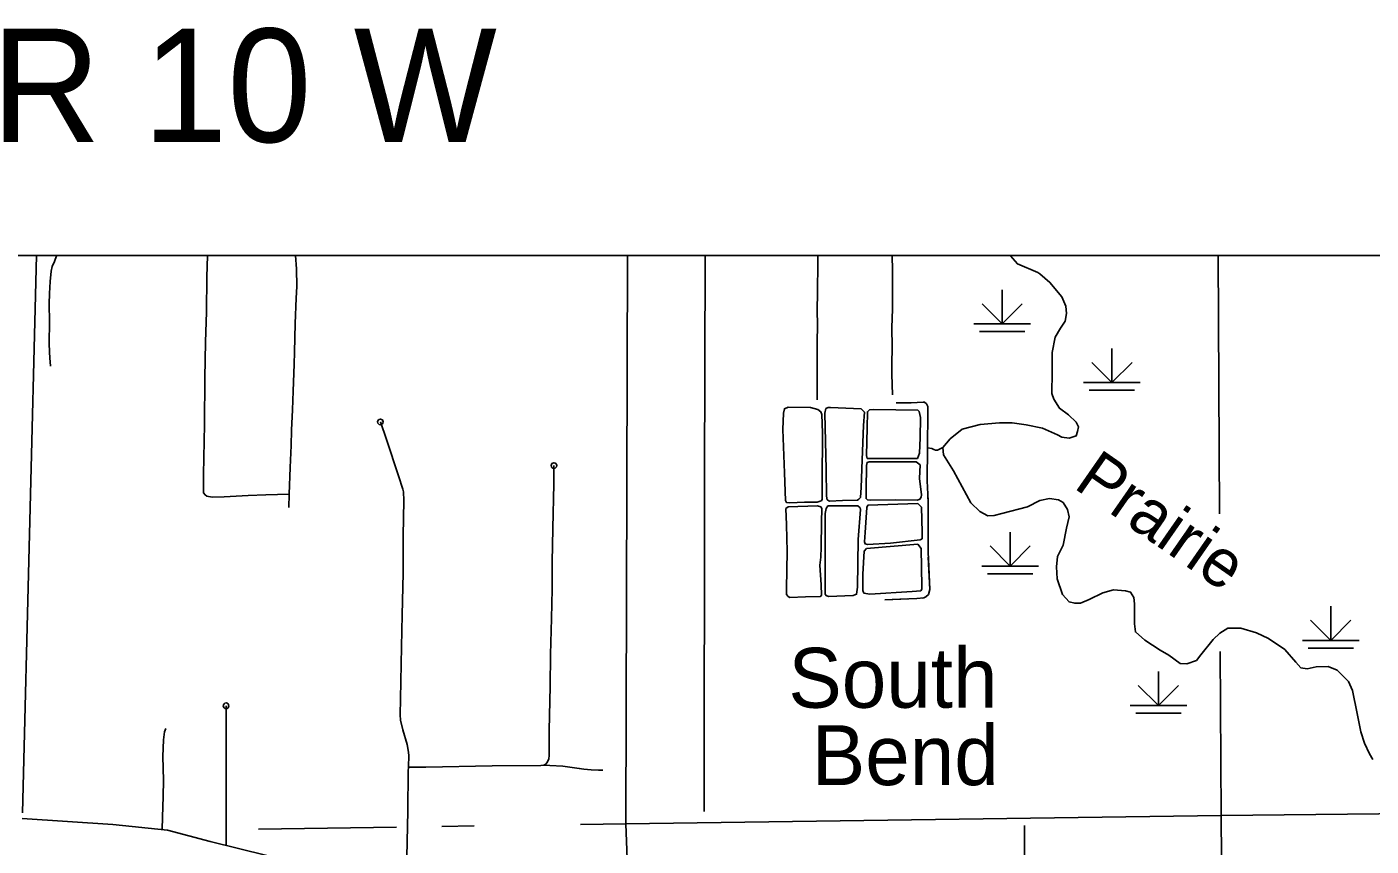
# Model space of a CAD drawing. Extents: x 1127717 to 1741049, y 2026793 to 2244711.
# Drawn here: x 1289221 to 1301075, y 2106736 to 2113957 of the extents above; entities that cross this region are included whole.
import ezdxf

# ---------------------------------------------------------------- set-up
doc = ezdxf.new("R2010")
doc.units = 0
for name, color, linetype in [('1', 7, 'Continuous'), ('10', 7, 'Continuous'), ('2', 7, 'Continuous'), ('24', 7, 'Continuous'), ('31', 7, 'Continuous'), ('32', 7, 'Continuous'), ('35', 7, 'Continuous'), ('43', 7, 'Continuous'), ('44', 7, 'Continuous'), ('5', 7, 'Continuous'), ('R_Draft', 7, 'Continuous')]:
    doc.layers.add(name, color=color, linetype=linetype)

msp = doc.modelspace()

# ---------------------------------------------------------------- linework, layer by layer
at = {"layer": '1'}
msp.add_lwpolyline([(1349634, 2111942), (1278363, 2111942), (1278363, 2066677), (1349634, 2066677)], close=True, dxfattribs=at)
at = {"layer": '10'}
msp.add_lwpolyline([(1289179, 2106981), (1289979, 2106928), (1290461, 2106877), (1290836, 2106777), (1291337, 2106654)], dxfattribs=at)
at = {"layer": '2'}
msp.add_lwpolyline([(1289181, 2107030), (1289306, 2111942)], dxfattribs=at)
at = {"layer": '31'}
for points in [[(1289483, 2111942), (1289482, 2111938), (1289464, 2111889), (1289443, 2111844), (1289435, 2111803), (1289427, 2111713), (1289421, 2111608), (1289417, 2111517), (1289419, 2111357), (1289417, 2111169), (1289419, 2111091), (1289423, 2111041), (1289429, 2110967)], [(1290813, 2111942), (1290809, 2111750), (1290805, 2111445), (1290797, 2111178), (1290791, 2110864), (1290787, 2110454), (1290779, 2110013), (1290777, 2109880), (1290779, 2109851), (1290793, 2109832), (1290807, 2109822), (1290855, 2109812), (1290960, 2109815)], [(1291531, 2109720), (1291533, 2109839), (1291544, 2110073), (1291552, 2110267), (1291554, 2110403), (1291562, 2110581), (1291568, 2110746), (1291578, 2110983), (1291580, 2111090), (1291587, 2111344), (1291595, 2111566), (1291601, 2111668), (1291599, 2111826), (1291591, 2111942)], [(1296197, 2111942), (1296197, 2111868), (1296193, 2111629), (1296190, 2111448), (1296192, 2111339), (1296190, 2111167), (1296190, 2111080), (1296190, 2111054), (1296189, 2110929), (1296190, 2110798), (1296189, 2110670)], [(1296851, 2111942), (1296854, 2111809), (1296854, 2111471), (1296850, 2111304), (1296851, 2111137), (1296851, 2111075), (1296850, 2111044), (1296850, 2110896), (1296854, 2110713)], [(1292338, 2110475), (1292391, 2110321), (1292498, 2109999), (1292537, 2109884), (1292543, 2109859), (1292546, 2109782), (1292538, 2109470), (1292540, 2109142), (1292531, 2108776), (1292523, 2108492), (1292515, 2108036), (1292514, 2107893), (1292517, 2107846), (1292535, 2107760), (1292574, 2107631), (1292584, 2107583), (1292589, 2107537), (1292585, 2107433)], [(1292585, 2107433), (1292740, 2107433), (1293325, 2107443), (1293752, 2107446), (1293779, 2107450), (1293796, 2107460), (1293811, 2107478), (1293823, 2107507), (1293826, 2107534), (1293827, 2107604), (1293828, 2107759), (1293835, 2108144), (1293839, 2108424), (1293846, 2108744), (1293852, 2109001), (1293852, 2109240), (1293858, 2109537), (1293867, 2109930), (1293869, 2110090)], [(1290960, 2109815), (1291171, 2109827), (1291328, 2109833), (1291533, 2109839)], [(1290978, 2106742), (1290977, 2107973)], [(1290446, 2107773), (1290434, 2107745), (1290425, 2107673), (1290421, 2107525), (1290425, 2107318), (1290423, 2107173), (1290418, 2106991), (1290415, 2106882)], [(1292567, 2106372), (1292579, 2107043), (1292584, 2107396), (1292585, 2107433)], [(1293779, 2107450), (1293834, 2107448), (1293948, 2107440), (1294092, 2107421), (1294133, 2107414), (1294198, 2107408), (1294263, 2107407), (1294301, 2107406)]]:
    msp.add_lwpolyline(points, dxfattribs=at)
for centre in [(1292338, 2110475), (1293869, 2110090), (1290977, 2107973)]:
    msp.add_circle(centre, 25, dxfattribs=at)
at = {"layer": '32'}
for points in [[(1295202, 2111942), (1295198, 2109982), (1295193, 2107042)], [(1298020, 2106919), (1298020, 2106725), (1298020, 2106368), (1298020, 2106128)]]:
    msp.add_lwpolyline(points, dxfattribs=at)
at = {"layer": '35'}
for points in [[(1297894, 2111942), (1297895, 2111939), (1297956, 2111868), (1298135, 2111792)], [(1298135, 2111792), (1298155, 2111781), (1298243, 2111705), (1298348, 2111579), (1298382, 2111495), (1298390, 2111432), (1298378, 2111364), (1298336, 2111301), (1298289, 2111221), (1298264, 2111087), (1298264, 2110914), (1298260, 2110727), (1298277, 2110676), (1298327, 2110596), (1298407, 2110537), (1298475, 2110474), (1298496, 2110432), (1298487, 2110390), (1298475, 2110352), (1298411, 2110331), (1298348, 2110340), (1298310, 2110361), (1298176, 2110420), (1298033, 2110449), (1297911, 2110466), (1297797, 2110466), (1297629, 2110453), (1297469, 2110411), (1297364, 2110327), (1297297, 2110251), (1297305, 2110184), (1297393, 2110043), (1297545, 2109761), (1297625, 2109685), (1297696, 2109647), (1297751, 2109651), (1297818, 2109668), (1298045, 2109727), (1298155, 2109782)], [(1295933, 2110604), (1295901, 2110591), (1295892, 2110554), (1295886, 2110410), (1295903, 2110026), (1295910, 2109782), (1295921, 2109765), (1295948, 2109761), (1296079, 2109769), (1296189, 2109769), (1296216, 2109776), (1296227, 2109780), (1296234, 2109794), (1296235, 2109941), (1296236, 2110378), (1296230, 2110542), (1296221, 2110565), (1296196, 2110584), (1296130, 2110602)], [(1296130, 2110602), (1295933, 2110604)], [(1296577, 2110591), (1296307, 2110602), (1296287, 2110602), (1296267, 2110593), (1296258, 2110552), (1296270, 2110057), (1296272, 2109822), (1296279, 2109790), (1296298, 2109778), (1296413, 2109782), (1296545, 2109785), (1296559, 2109795), (1296571, 2109808), (1296577, 2109898), (1296588, 2110141), (1296599, 2110443), (1296607, 2110562)], [(1296607, 2110562), (1296577, 2110591)], [(1296631, 2110154), (1296624, 2110179), (1296631, 2110424), (1296634, 2110565), (1296652, 2110582), (1296691, 2110584), (1297077, 2110579), (1297091, 2110566), (1297100, 2110513), (1297099, 2110335), (1297094, 2110201), (1297074, 2110154)], [(1297163, 2110246), (1297202, 2110241), (1297220, 2110232), (1297234, 2110226), (1297250, 2110227), (1297297, 2110251)], [(1296648, 2110123), (1296630, 2110118), (1296624, 2110092), (1296621, 2109878), (1296621, 2109799), (1296633, 2109790), (1296657, 2109787), (1296884, 2109789), (1297076, 2109785), (1297096, 2109794), (1297108, 2109813), (1297109, 2109834), (1297094, 2109976), (1297099, 2110096), (1297064, 2110124)], [(1297074, 2110154), (1296631, 2110154)], [(1297064, 2110124), (1296648, 2110123)], [(1296637, 2109743), (1296628, 2109722), (1296612, 2109500), (1296608, 2109418), (1296612, 2109400), (1296634, 2109394), (1296837, 2109407), (1297097, 2109436), (1297116, 2109446), (1297116, 2109504), (1297109, 2109725), (1297079, 2109755)], [(1297079, 2109755), (1296637, 2109743)], [(1298155, 2109782), (1298239, 2109799), (1298319, 2109790), (1298361, 2109765), (1298399, 2109702), (1298411, 2109639), (1298390, 2109538), (1298361, 2109390), (1298310, 2109289), (1298302, 2109197), (1298306, 2109091), (1298353, 2108953), (1298411, 2108889), (1298462, 2108877), (1298512, 2108877), (1298588, 2108910), (1298710, 2108969), (1298803, 2108995), (1298908, 2108986), (1298954, 2108974), (1298984, 2108927), (1298988, 2108873), (1298988, 2108788), (1298988, 2108696), (1298996, 2108624), (1299080, 2108553), (1299215, 2108464), (1299291, 2108418), (1299392, 2108347), (1299451, 2108342), (1299535, 2108372), (1299573, 2108422), (1299682, 2108557), (1299741, 2108612), (1299812, 2108658), (1299926, 2108658), (1300065, 2108616), (1300170, 2108565), (1300313, 2108469), (1300410, 2108359), (1300456, 2108309), (1300511, 2108300), (1300591, 2108317), (1300696, 2108321), (1300776, 2108288), (1300877, 2108187), (1300910, 2108107), (1300953, 2107905), (1300986, 2107745), (1301016, 2107644), (1301062, 2107551), (1301091, 2107501)], [(1295934, 2109726), (1295915, 2109711), (1295921, 2109567), (1295925, 2109334), (1295920, 2109007), (1295920, 2108954), (1295933, 2108937), (1295948, 2108929), (1296088, 2108933), (1296220, 2108937), (1296229, 2108948), (1296225, 2109040), (1296214, 2109214), (1296223, 2109282), (1296225, 2109371), (1296229, 2109591), (1296230, 2109711), (1296222, 2109728), (1296192, 2109737)], [(1296192, 2109737), (1295934, 2109726)], [(1296285, 2109737), (1296269, 2109712), (1296262, 2109668), (1296261, 2109308), (1296260, 2108994), (1296261, 2108958), (1296269, 2108945), (1296291, 2108937), (1296509, 2108944), (1296538, 2108957), (1296546, 2109020), (1296553, 2109440), (1296572, 2109703), (1296569, 2109717), (1296549, 2109737)], [(1296549, 2109737), (1296285, 2109737)], [(1296625, 2109361), (1296604, 2109336), (1296593, 2109132), (1296593, 2108988), (1296603, 2108967), (1296655, 2108958), (1297029, 2108980), (1297103, 2108986), (1297114, 2109002), (1297114, 2109025), (1297107, 2109361), (1297077, 2109397)], [(1297077, 2109397), (1296625, 2109361)]]:
    msp.add_lwpolyline(points, dxfattribs=at)
at = {"layer": '43'}
for points in [[(1296788, 2108907), (1297070, 2108920), (1297132, 2108924), (1297149, 2108935), (1297171, 2108955), (1297183, 2108997), (1297168, 2109330), (1297168, 2109779), (1297161, 2109956), (1297163, 2110246), (1297165, 2110563), (1297165, 2110612), (1297154, 2110635), (1297136, 2110649), (1297126, 2110649), (1297019, 2110643), (1296888, 2110643)], [(1297161, 2109944), (1297161, 2109956), (1297163, 2110246), (1297164, 2110340)], [(1297168, 2109416), (1297168, 2109779), (1297167, 2109812)], [(1297117, 2108923), (1297132, 2108924), (1297149, 2108935), (1297171, 2108955), (1297183, 2108997), (1297170, 2109284)], [(1296788, 2108907), (1296985, 2108917)]]:
    msp.add_lwpolyline(points, dxfattribs=at)
at = {"layer": '44'}
for p, q in [((1297822, 2111639), (1297822, 2111339)), ((1297822, 2111339), (1297645, 2111516)), ((1297822, 2111339), (1297998, 2111516)), ((1297572, 2111339), (1298072, 2111339)), ((1297622, 2111271), (1298022, 2111271)), ((1298790, 2111123), (1298790, 2110823)), ((1298790, 2110823), (1298613, 2111000)), ((1298790, 2110823), (1298967, 2111000)), ((1298540, 2110823), (1299040, 2110823)), ((1298590, 2110755), (1298990, 2110755)), ((1297892, 2109505), (1297892, 2109205)), ((1297892, 2109205), (1297715, 2109382)), ((1297892, 2109205), (1298069, 2109382)), ((1297642, 2109205), (1298142, 2109205)), ((1297692, 2109137), (1298092, 2109137)), ((1300719, 2108850), (1300719, 2108550)), ((1300719, 2108550), (1300542, 2108727)), ((1300719, 2108550), (1300896, 2108727)), ((1300469, 2108550), (1300969, 2108550)), ((1300519, 2108482), (1300919, 2108482)), ((1299199, 2108276), (1299199, 2107976)), ((1299199, 2107976), (1299022, 2108153)), ((1299199, 2107976), (1299376, 2108153)), ((1298949, 2107976), (1299449, 2107976)), ((1298999, 2107908), (1299399, 2107908))]:
    msp.add_line(p, q, dxfattribs=at)
at = {"layer": '5'}
for points in [[(1294502, 2106934), (1294518, 2111942)], [(1299727, 2111942), (1299739, 2109665)], [(1299745, 2108452), (1299752, 2107006)], [(1299752, 2107006), (1305040, 2107063)], [(1292879, 2106910), (1293164, 2106914)], [(1294102, 2106928), (1294502, 2106934)], [(1294502, 2106934), (1299752, 2107006)], [(1294664, 2102677), (1294502, 2106934)], [(1299752, 2107006), (1299758, 2106250)], [(1291263, 2106886), (1292479, 2106904)]]:
    msp.add_lwpolyline(points, dxfattribs=at)

# ---------------------------------------------------------------- texts
at = {"layer": '24'}
for s, p in [('South', (1295936, 2107956)), ('Bend', (1296143, 2107274))]:
    msp.add_text(s, height=528, dxfattribs=at).set_placement(p)
at = {"layer": '35'}
msp.add_text('Prairie', height=422.4, rotation=325.1868, dxfattribs=at).set_placement((1298440, 2109900))
at = {"layer": 'R_Draft'}
msp.add_text('R 10 W', height=1000, dxfattribs=at).set_placement((1288907, 2112942))

doc.saveas('drawing.dxf')
